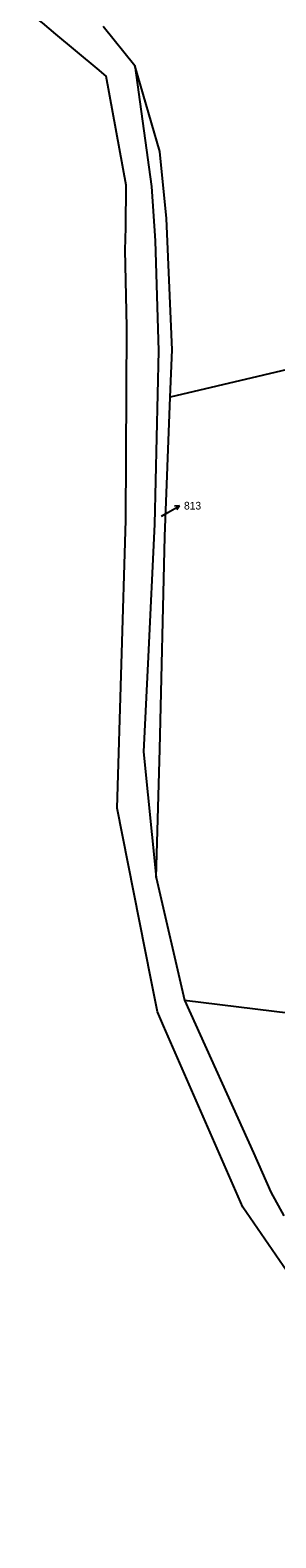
# Model space of a CAD drawing. Extents: x -887272 to -880188, y -1026687 to -1021896.
# Drawn here: x -886195.1 to -886140.7, y -1024866.4 to -1024532.4 of the extents above; entities that cross this region are included whole.
import ezdxf

# ---------------------------------------------------------------- set-up
doc = ezdxf.new("R2010")
doc.units = 0
for name, color, linetype in [('Hranice parcel', 7, 'Continuous'), ('Parcelní čísla', 7, 'Continuous'), ('Pop  PČ popisy', 7, 'Continuous')]:
    doc.layers.add(name, color=color, linetype=linetype)

msp = doc.modelspace()

# ---------------------------------------------------------------- linework, layer by layer
at = {"layer": 'Hranice parcel'}
for p, q in [((-886178.96, -1024531.47), (-886171.88, -1024540.22)), ((-886180.28, -1024540.87), (-886189.42, -1024533.25)), ((-885988.93, -1024572.09), (-886164.05, -1024613.72)), ((-886173.85, -1024591.22), (-886174.06, -1024581.14)), ((-886173.7, -1024598.21), (-886173.85, -1024591.22)), ((-886165.29, -1024644.59), (-886164.05, -1024613.72)), ((-886167.16, -1024720.14), (-886160.87, -1024747.28))]:
    msp.add_line(p, q, dxfattribs=at)
for points in [[(-886189.42, -1024533.25), (-886192.4, -1024530.76), (-886195.1, -1024528.68)], [(-886174.06, -1024581.14), (-886173.92, -1024576.06), (-886173.86, -1024566.74), (-886178.26, -1024542.56), (-886180.28, -1024540.87)], [(-886164.05, -1024613.72), (-886163.64, -1024603.16), (-886164.64, -1024579.2), (-886164.9, -1024574.1), (-886166.4, -1024559.28), (-886171.88, -1024540.22)], [(-886171.88, -1024540.22), (-886168.24, -1024567.02), (-886167.44, -1024579.04), (-886166.66, -1024603.44), (-886167.58, -1024641.86), (-886168.98, -1024671.2), (-886169.96, -1024692.3), (-886167.16, -1024720.14)], [(-886168.34, -1024742.53), (-886175.86, -1024704.72), (-886173.88, -1024640.94), (-886173.7, -1024598.21)], [(-886167.16, -1024720.14), (-886166.38, -1024691.66), (-886165.29, -1024644.59)], [(-886165.53, -1024752.98), (-886166.88, -1024749.88), (-886168.34, -1024742.53)], [(-886160.87, -1024747.28), (-886121.76, -1024752.1), (-886099.92, -1024753.68), (-886061.64, -1024748.62), (-886061.4, -1024769)], [(-886160.87, -1024747.28), (-886145.62, -1024781.1), (-886141.78, -1024789.88), (-886138.89, -1024795.08)], [(-886083.42, -1024866.44), (-886127.7, -1024822.72), (-886147.98, -1024793.2), (-886165.53, -1024752.98)]]:
    msp.add_lwpolyline(points, dxfattribs=at)
at = {"layer": 'Pop  PČ popisy'}
for p, q in [((-886166.01, -1024640.03), (-886164.62, -1024639.23)), ((-886164.62, -1024639.23), (-886162.02, -1024637.73)), ((-886162.02, -1024637.73), (-886163.14, -1024637.8)), ((-886162.02, -1024637.73), (-886162.64, -1024638.66))]:
    msp.add_line(p, q, dxfattribs=at)

# ---------------------------------------------------------------- texts
at = {"layer": 'Parcelní čísla'}
msp.add_text('813', height=1.7, dxfattribs=at).set_placement((-886161.02, -1024638.58))

doc.saveas('drawing.dxf')
